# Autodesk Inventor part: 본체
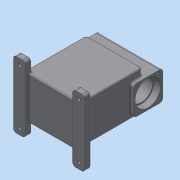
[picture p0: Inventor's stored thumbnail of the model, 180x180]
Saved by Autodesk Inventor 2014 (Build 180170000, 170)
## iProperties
Created: 2025-06
Part Number: 본체
Material: 일반
Document SubType Name: Modeling
Designer: dg
Density: 1 g/cm^3
Appearance: 기본값
Mass: 2964.21 g
Surface Area: 3446.07 cm^2
Volume: 2964.21 cm^3
Author: dg
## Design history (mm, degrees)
sketch "스케치1"
  geometry: L1 (-93, -103)-(93, -103); L2 (93, -103)-(93, 103); L3 (93, 103)-(-93, 103); L4 (-93, 103)-(-93, -103); L5 (-93, -103)-(93, 103); L6 (93, -103)-(-93, 103); 1 further point
  constraints: 12 end point, 2 midpoint, 2 parallel, 1 horizontal, 1 perpendicular
  dimensions: "d0" = 186 distance of L3.end L2.end; "d1" = 206 distance of L2.end L1.end
extrude "돌출1" new body sketch "스케치1" stored distance "d2" = 140; taper "d3" = 0 deg
sketch "스케치2"
  geometry: L1 (140, 206)-(0, 206) reference; L2 (140, 206)-(140, 0) reference; L3 (125, 206)-(125, 17); L4 (125, 17)-(140, 17); 1 further point
  constraints: 4 end point, 2 point on line, 1 parallel, 1 perpendicular
  dimensions: "d4" = 189 distance between parallel lines of L1 L4; "d5" = 15 distance of L3.end L4.end
extrude "돌출2" cut sketch "스케치2" stored distance "d6" = 140; taper "d7" = 0 deg
node "작업 평면2"
sketch "스케치6"
  geometry: L1 (-25, -180)-(211, -180); L2 (211, -180)-(211, 40); L3 (211, 40)-(-25, 40); L4 (-25, 40)-(-25, -180); L5 (-25, -180)-(211, 40); L6 (211, -180)-(-25, 40); 1 further point
  constraints: 12 end point, 2 midpoint, 2 parallel, 1 horizontal, 1 perpendicular
  dimensions: "d18" = 220 distance of L1.end L2.end; "d19" = 236 distance of L2.end L3.end
extrude "돌출4" join sketch "스케치6" distance "d20" = 20; taper "d21" = 0 deg
sketch "스케치7"
  geometry: L1 (236, 0)-(0, 0) reference; L2 (236, 0)-(236, 20) reference; L3 (0, 20)-(236, 20) reference; L4 (0, 0)-(0, 20) reference; L5 (40, 10)-(40, 0); L6 (196, 10)-(196, 0); L7 (40, 10)-(196, 10); 1 further point
  constraints: 6 end point, 4 perpendicular, 2 point on line, 1 parallel
  dimensions: "d22" = 40 distance between parallel lines of L4 L5; "d23" = 40 distance between parallel lines of L2 L6; "d127" = 10 distance between parallel lines of L1 L7
extrude "돌출5" cut sketch "스케치7" stored distance "d24" = 20; taper "d25" = 0 deg
node "작업 평면4"
sketch "스케치13"
  geometry: L1 (62, 48)-(158, 48); L2 (158, 48)-(158, -48); L3 (158, -48)-(62, -48); L4 (62, -48)-(62, 48); L5 (62, 48)-(158, -48); L6 (158, 48)-(62, -48); L7 (-113, -110)-(-113, 110) reference; L8 (-93, 70)-(103, 70) reference; L9 (-86, -55)-(103, -55) reference; L10 (-113, 110)-(-93, 110) reference; 5 further points
  constraints: 12 end point, 4 midpoint, 2 parallel, 1 horizontal, 1 horizontal alignment, 1 perpendicular
  dimensions: "d52" = 96 distance of L2.end L3.end; "d53" = 96 distance of L1.end L2.end; "d54" = 223 distance from line of L7 point (110, 0)
extrude "돌출6" join sketch "스케치13" distance "d56" = 210; taper "d57" = 0 deg
sketch "스케치14"
  geometry: L1 (48, 158)-(-48, 158) reference; L2 (-48, 158)-(-48, 62) reference; 4 further points
  constraints: 2 midpoint, 1 horizontal alignment, 1 vertical alignment
hole "구멍4" sketch "스케치14" at (0, 110) diameter "d58" = 85; stored, may be unused: countersink angle "d62" = 90 deg, drill point angle "d64" = 0 deg; dims "d59" = 6, "d60" = 62, "d61" = 16, "d63" = 23
fillet "모깎기1" dims "d72" = 1.1
chamfer "모따기1" distance "d73" = 1; stored, may be unused: second distance "d74" = 2, angle "d75" = 45 deg
fillet "모깎기2" dims "d76" = 10
sketch "스케치16"
  geometry: A1 r 10 centre (-38, 148) between (-38, 158) and (-48, 148) reference; 1 further point
hole "구멍6" sketch "스케치16" at (-38, 148) diameter "d77" = 4.917; stored, may be unused: countersink angle "d81" = 90 deg, drill point angle "d83" = 118 deg; dims "d78" = 12, "d79" = 62, "d80" = 16, "d82" = 14
sketch "스케치17"
  geometry: L1 (211, 180)-(-25, 180) reference; 4 further points
  constraints: 2 vertical alignment, 1 point on line
  dimensions: "d93" = 180 distance of point (191, 160) point (191, -20); "d94" = 90 vertical distance of point (93, 70) point (191, 160)
hole "구멍7" sketch "스케치17" at (191, 160), (191, -20) diameter "d95" = 11; stored, may be unused: countersink angle "d99" = 90 deg, drill point angle "d101" = 118 deg; dims "d96" = 16, "d97" = 28, "d98" = 2, "d100" = 18
sketch "스케치18"
  geometry: L1 (198, 55)-(-12, 55) reference; 2 further points
  constraints: 1 vertical alignment, 1 other
  dimensions: "d102" = 30 distance from line of point (93, 25) L1
feature "엠보싱1" sketch "스케치18" dims "d103" = 0.5, "d104" = 0
fillet "모깎기6" dims "d117" = 10
fillet "모깎기8" dims "d119" = 3
fillet "모깎기9" dims "d120" = 10
fillet "모깎기10" dims "d121" = 3
sketch "스케치22"
  geometry: L1 (0, 0)-(236, 0) reference; L2 (40, -10)-(196, -10) reference; L3 (40, -10)-(40, 0); L4 (196, -10)-(196, 0); 1 further point
  constraints: 4 end point, 2 perpendicular, 2 point on line
extrude "돌출8" cut sketch "스케치22" stored distance "d130" = 210; taper "d131" = 0 deg
sketch "스케치23"
  geometry: L1 (40, -10)-(196, -10) reference; L2 (0, 0)-(236, 0) reference; L3 (40, -20)-(0, -20) reference; L4 (40, -10)-(40, 0); L5 (196, -10)-(196, 0); 1 further point
  constraints: 4 end point, 2 perpendicular, 2 point on line
extrude "돌출9" cut sketch "스케치23" stored distance "d132" = 210; taper "d133" = 0 deg
fillet "모깎기16" dims "d134" = 10
fillet "모깎기17" dims "d135" = 3
fillet "모깎기18" dims "d136" = 3
fillet "모깎기19" dims "d137" = 3
fillet "모깎기20" dims "d138" = 3
sketch "스케치26"
  geometry: C1 r 41.4 at (0, 0) reference; 1 further point
hole "구멍9" sketch "스케치26" at (0, 0) diameter "d142" = 77; stored, may be unused: countersink angle "d146" = 90 deg, drill point angle "d148" = 0 deg; dims "d143" = 16, "d144" = 28, "d145" = 2, "d147" = 18
sketch "스케치28"
  geometry: L1 (5, -27)-(-15, -27) reference; 2 further points
  constraints: 1 vertical alignment
  dimensions: "d161" = 123 distance from line of L1 point (93, 96)
hole "구멍11" sketch "스케치28" at (93, 96) diameter "d162" = 172; stored, may be unused: countersink angle "d166" = 90 deg, drill point angle "d168" = 0 deg; dims "d163" = 16, "d164" = 28, "d165" = 2, "d167" = 102
sketch "스케치29"
  geometry: C1 r 86 at (0, 0) reference; 1 further point
hole "구멍12" sketch "스케치29" at (0, 0) diameter "d169" = 62; stored, may be unused: countersink angle "d173" = 90 deg, drill point angle "d175" = 0 deg; dims "d170" = 16, "d171" = 28, "d172" = 2, "d174" = 16
sketch "스케치30"
  geometry: C1 r 31 at (0, 0) reference; 1 further point
hole "구멍13" sketch "스케치30" at (0, 0) diameter "d176" = 54; stored, may be unused: countersink angle "d180" = 90 deg, drill point angle "d182" = 0 deg; dims "d177" = 16, "d178" = 28, "d179" = 2, "d181" = 3
chamfer "모따기3" distance "d183" = 1; stored, may be unused: second distance "d184" = 2, angle "d185" = 45 deg
chamfer "모따기4" distance "d186" = 1; stored, may be unused: second distance "d187" = 2, angle "d188" = 45 deg
fillet "모깎기21" dims "d189" = 1
fillet "모깎기22" dims "d190" = 3
sketch "스케치31"
  geometry: C1 r 87 at (93, 96) reference; 2 further points
  dimensions: "d191" = 75 horizontal distance of C1.centre point (18, 171); "d192" = 75 horizontal distance of C1.centre point (18, 171)
hole "구멍14" sketch "스케치31" at (18, 171) diameter "d193" = 6.647; stored, may be unused: countersink angle "d197" = 90 deg, drill point angle "d199" = 118 deg; dims "d194" = 16, "d195" = 28, "d196" = 2, "d198" = 18
node "솔리드1"
mirror "대칭1"
mirror "대칭2"
mirror "대칭3"
pattern_circular "원형 패턴4" dims angle "d201" = 360 deg
pattern_circular "원형 패턴5" dims angle "d204" = 360 deg
mirror "대칭4"
other parameters: "d51" = 105
